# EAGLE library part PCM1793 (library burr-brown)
AUDIO STEREO DIGITAL-TO-ANALOG CONVERTER 24-BIT, 192-kHz SAMPLING, ADVANCED SEGMENT Source: http://focus.ti.com/lit/ds/symlink/pcm1793.pdf
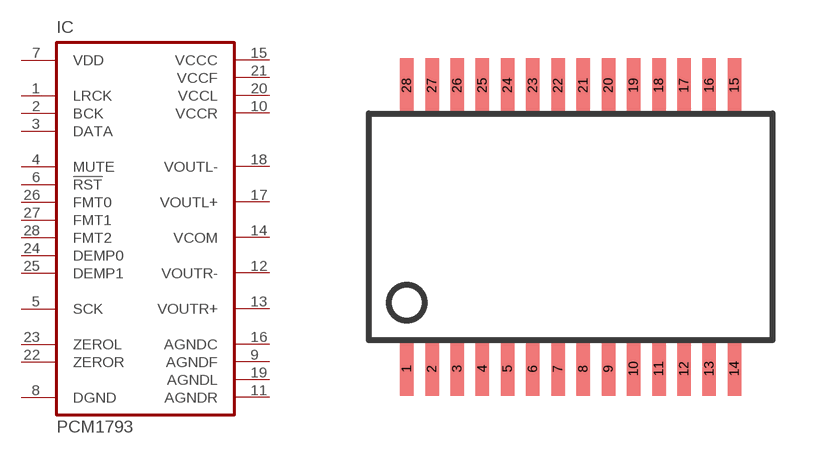
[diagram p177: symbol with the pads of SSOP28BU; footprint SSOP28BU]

Designator prefix IC

## PCM1793 (MF: TEXAS INSTRUMENT CONNECTORS; MPN: PCM1793DBR; OC_FARNELL: 1408322; OC_NEWARK: 61H5174)  [SSOP28BU]
1  LRCK  in
2  BCK  in
3  DATA  in
4  MUTE  in
5  SCK  in
6  !RST  in
7  VDD  pwr
8  DGND  pwr
9  AGNDF  pwr
10  VCCR  pwr
11  AGNDR  pwr
12  VOUTR-  out
13  VOUTR+  out
14  VCOM  pas
15  VCCC  pwr
16  AGNDC  pwr
17  VOUTL+  out
18  VOUTL-  out
19  AGNDL  pwr
20  VCCL  pwr
21  VCCF  pwr
22  ZEROR  out
23  ZEROL  out
24  DEMP0  in
25  DEMP1  in
26  FMT0  in
27  FMT1  in
28  FMT2  in

## Footprint SSOP28BU (pad centres in mm)
Small Shrink Outline Package
smd 0.348 x 1.397: 1 -4.225,-3.656; 2 -3.575,-3.656; 3 -2.925,-3.656; 4 -2.275,-3.656; 5 -1.625,-3.656; 6 -0.975,-3.656; 7 -0.325,-3.656; 8 0.325,-3.656; 9 0.975,-3.656; 10 1.625,-3.656; 11 2.275,-3.656; 12 2.925,-3.656; 13 3.575,-3.656; 14 4.225,-3.656; 15 4.225,3.656; 16 3.575,3.656; 17 2.925,3.656; 18 2.275,3.656; 19 1.625,3.656; 20 0.975,3.656; 21 0.325,3.656; 22 -0.325,3.656; 23 -0.975,3.656; 24 -1.625,3.656; 25 -2.275,3.656; 26 -2.925,3.656; 27 -3.575,3.656; 28 -4.225,3.656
